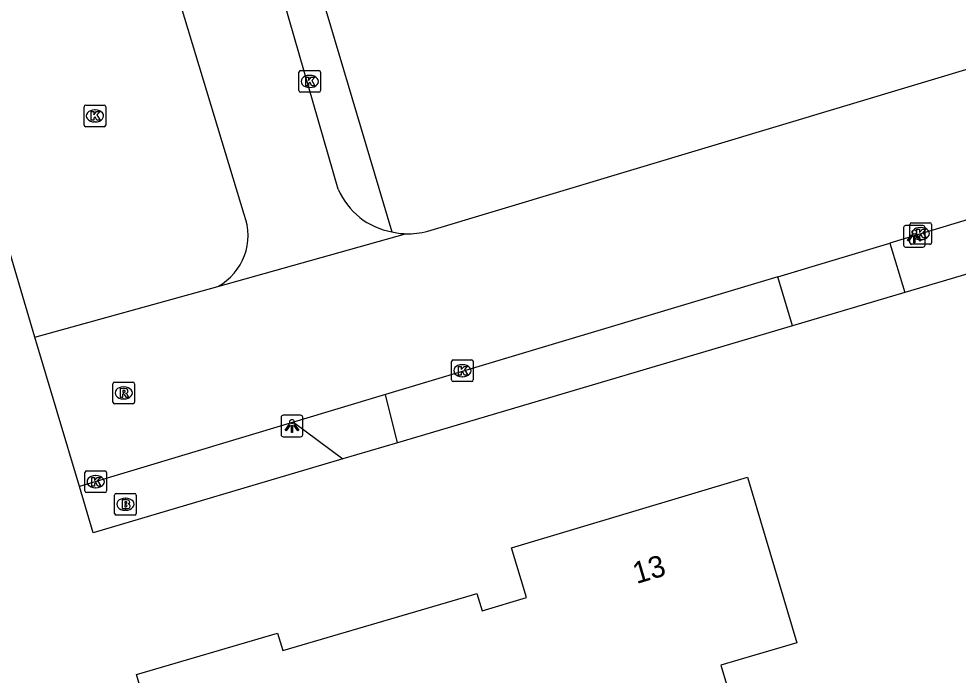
# Model space of a CAD drawing. Extents: x 162417 to 163721, y 384268 to 385416.
# Drawn here: x 163147.13 to 163190.63, y 385083.29 to 385113.7 of the extents above; entities that cross this region are included whole.
import ezdxf

# ---------------------------------------------------------------- set-up
doc = ezdxf.new("R2010")
doc.units = 0
for name, color, linetype in [('IMGEO_Brandkraan', 7, 'Continuous'), ('IMGEO_Groenvoorziening', 7, 'Continuous'), ('IMGEO_Kolk', 7, 'Continuous'), ('IMGEO_Lichtpunt', 7, 'Continuous'), ('IMGEO_Pand', 7, 'Continuous'), ('IMGEO_Pand_nummerreeks', 7, 'Continuous'), ('IMGEO_Parkeervlak_open', 7, 'Continuous'), ('IMGEO_Rijbaan_lokaal_gesloten', 7, 'Continuous'), ('IMGEO_Rioolput', 7, 'Continuous'), ('IMGEO_Voetpad_open', 7, 'Continuous')]:
    doc.layers.add(name, color=color, linetype=linetype)

msp = doc.modelspace()

# ---------------------------------------------------------------- linework, layer by layer
at = {"layer": 'IMGEO_Brandkraan'}
for p, q in [((163151.642, 385091.713), (163152.494, 385091.713)), ((163151.567, 385090.787), (163151.567, 385091.639)), ((163152.055, 385091.493), (163152.08, 385091.493)), ((163152.568, 385091.639), (163152.568, 385090.787)), ((163152.078, 385090.933), (163152.053, 385090.933)), ((163152.494, 385090.713), (163151.642, 385090.713))]:
    msp.add_line(p, q, dxfattribs=at)
for points in [[(163151.642, 385091.713), (163152.494, 385091.713)], [(163151.567, 385090.787), (163151.567, 385091.639)], [(163151.915, 385091.413), (163151.915, 385091.013), (163152.128, 385091.013)], [(163152.146, 385091.413), (163151.915, 385091.413)], [(163152.094, 385091.332), (163152.04, 385091.332), (163152.04, 385091.256)], [(163152.04, 385091.256), (163152.093, 385091.256)], [(163152.568, 385091.639), (163152.568, 385090.787)], [(163152.102, 385091.18), (163152.04, 385091.18), (163152.04, 385091.099)], [(163152.04, 385091.099), (163152.102, 385091.099)], [(163152.494, 385090.713), (163151.642, 385090.713)]]:
    msp.add_lwpolyline(points, dxfattribs=at)
for centre, radius, start, end in [((163151.644, 385091.637), 0.0765, 91.552, 178.448), ((163151.644, 385091.637), 0.0765, 91.552, 178.448), ((163152.492, 385091.637), 0.0765, 1.552, 88.448), ((163152.492, 385091.637), 0.0765, 1.552, 88.448), ((163152.095, 385091.294), 0.0379, 267.8285, 90.9355), ((163152.15, 385091.268), 0.145, 59.4692, 91.5367), ((163152.175, 385091.315), 0.0922, 285.5137, 58.1501), ((163152.103, 385091.139), 0.0404, 269.8759, 90.5077), ((163152.134, 385091.264), 0.251, 268.6676, 293.5347), ((163152.18, 385091.123), 0.105, 301.3115, 78.989), ((163151.644, 385090.789), 0.0765, 181.552, 268.448), ((163151.644, 385090.789), 0.0765, 181.552, 268.448), ((163152.492, 385090.789), 0.0765, 271.552, 358.448), ((163152.492, 385090.789), 0.0765, 271.552, 358.448)]:
    msp.add_arc(centre, radius, start, end, dxfattribs=at)
for centre, major_axis, ratio, start_param, end_param in [((163152.054, 385091.213), (-0.387, 0.002), 0.722429, 4.712389, 7.853982), ((163152.079, 385091.213), (-0.39, 0.002), 0.717154, 1.570796, 4.712389)]:
    msp.add_ellipse(centre, major_axis=major_axis, ratio=ratio, start_param=start_param, end_param=end_param, dxfattribs=at)
at = {"layer": 'IMGEO_Groenvoorziening'}
for points in [[(163159.712, 385119.619), (163164.406, 385103.831)], [(163196.923, 385103.613), (163194.213, 385102.811), (163188.152, 385101.016)], [(163182.959, 385099.479), (163164.667, 385094.062)], [(163162.132, 385093.311), (163150.576, 385089.889), (163149.939, 385092.03)]]:
    msp.add_lwpolyline(points, dxfattribs=at)
at = {"layer": 'IMGEO_Kolk'}
for p, q in [((163160.174, 385111.302), (163161.026, 385111.302)), ((163160.099, 385110.376), (163160.099, 385111.228)), ((163160.587, 385111.082), (163160.612, 385111.082)), ((163161.1, 385111.228), (163161.1, 385110.376)), ((163160.61, 385110.522), (163160.585, 385110.522)), ((163161.026, 385110.302), (163160.174, 385110.302)), ((163150.154, 385108.777), (163150.154, 385109.629)), ((163150.229, 385109.703), (163151.081, 385109.703)), ((163151.155, 385109.629), (163151.155, 385108.777)), ((163150.642, 385109.483), (163150.667, 385109.483)), ((163151.081, 385108.703), (163150.229, 385108.703)), ((163150.665, 385108.923), (163150.64, 385108.923)), ((163188.394, 385103.329), (163188.394, 385104.181)), ((163188.469, 385104.255), (163189.321, 385104.255)), ((163188.882, 385104.035), (163188.907, 385104.035)), ((163189.395, 385104.181), (163189.395, 385103.329)), ((163188.905, 385103.475), (163188.88, 385103.475)), ((163189.321, 385103.255), (163188.469, 385103.255)), ((163167.171, 385096.974), (163167.171, 385097.826)), ((163167.246, 385097.9), (163168.098, 385097.9)), ((163168.172, 385097.826), (163168.172, 385096.974)), ((163167.659, 385097.68), (163167.684, 385097.68)), ((163168.098, 385096.9), (163167.246, 385096.9)), ((163167.682, 385097.12), (163167.657, 385097.12)), ((163150.188, 385091.832), (163150.188, 385092.684)), ((163150.263, 385092.758), (163151.115, 385092.758)), ((163150.676, 385092.538), (163150.701, 385092.538)), ((163151.189, 385092.684), (163151.189, 385091.832)), ((163151.115, 385091.758), (163150.263, 385091.758)), ((163150.699, 385091.978), (163150.674, 385091.978))]:
    msp.add_line(p, q, dxfattribs=at)
for points in [[(163160.174, 385111.302), (163161.026, 385111.302)], [(163160.099, 385110.376), (163160.099, 385111.228)], [(163160.42, 385111.002), (163160.543, 385111.002), (163160.543, 385110.851), (163160.673, 385111.002), (163160.837, 385111.002), (163160.691, 385110.851), (163160.844, 385110.602), (163160.692, 385110.602), (163160.607, 385110.766), (163160.543, 385110.699), (163160.543, 385110.602), (163160.42, 385110.602), (163160.42, 385111.002)], [(163161.1, 385111.228), (163161.1, 385110.376)], [(163161.026, 385110.302), (163160.174, 385110.302)], [(163150.154, 385108.777), (163150.154, 385109.629)], [(163150.229, 385109.703), (163151.081, 385109.703)], [(163151.155, 385109.629), (163151.155, 385108.777)], [(163150.475, 385109.403), (163150.598, 385109.403), (163150.598, 385109.252), (163150.728, 385109.403), (163150.892, 385109.403), (163150.746, 385109.252), (163150.899, 385109.003), (163150.747, 385109.003), (163150.662, 385109.167), (163150.598, 385109.1), (163150.598, 385109.003), (163150.475, 385109.003), (163150.475, 385109.403)], [(163151.081, 385108.703), (163150.229, 385108.703)], [(163188.394, 385103.329), (163188.394, 385104.181)], [(163188.469, 385104.255), (163189.321, 385104.255)], [(163188.715, 385103.955), (163188.838, 385103.955), (163188.838, 385103.804), (163188.968, 385103.955), (163189.132, 385103.955), (163188.986, 385103.804), (163189.139, 385103.555), (163188.987, 385103.555), (163188.902, 385103.719), (163188.838, 385103.652), (163188.838, 385103.555), (163188.715, 385103.555), (163188.715, 385103.955)], [(163189.395, 385104.181), (163189.395, 385103.329)], [(163189.321, 385103.255), (163188.469, 385103.255)], [(163167.171, 385096.974), (163167.171, 385097.826)], [(163167.246, 385097.9), (163168.098, 385097.9)], [(163168.172, 385097.826), (163168.172, 385096.974)], [(163167.492, 385097.6), (163167.615, 385097.6), (163167.615, 385097.449), (163167.745, 385097.6), (163167.909, 385097.6), (163167.763, 385097.449), (163167.916, 385097.2), (163167.764, 385097.2), (163167.679, 385097.364), (163167.615, 385097.297), (163167.615, 385097.2), (163167.492, 385097.2), (163167.492, 385097.6)], [(163168.098, 385096.9), (163167.246, 385096.9)], [(163150.188, 385091.832), (163150.188, 385092.684)], [(163150.263, 385092.758), (163151.115, 385092.758)], [(163151.189, 385092.684), (163151.189, 385091.832)], [(163150.509, 385092.458), (163150.632, 385092.458), (163150.632, 385092.307), (163150.762, 385092.458), (163150.926, 385092.458), (163150.78, 385092.307), (163150.933, 385092.058), (163150.781, 385092.058), (163150.696, 385092.222), (163150.632, 385092.155), (163150.632, 385092.058), (163150.509, 385092.058), (163150.509, 385092.458)], [(163151.115, 385091.758), (163150.263, 385091.758)]]:
    msp.add_lwpolyline(points, dxfattribs=at)
for centre, start, end in [((163160.176, 385111.226), 91.552, 178.448), ((163160.176, 385111.226), 91.552, 178.448), ((163161.024, 385111.226), 1.552, 88.448), ((163161.024, 385111.226), 1.552, 88.448), ((163160.176, 385110.378), 181.552, 268.448), ((163160.176, 385110.378), 181.552, 268.448), ((163161.024, 385110.378), 271.552, 358.448), ((163161.024, 385110.378), 271.552, 358.448), ((163150.231, 385109.627), 91.552, 178.448), ((163150.231, 385109.627), 91.552, 178.448), ((163151.079, 385109.627), 1.552, 88.448), ((163151.079, 385109.627), 1.552, 88.448), ((163150.231, 385108.779), 181.552, 268.448), ((163150.231, 385108.779), 181.552, 268.448), ((163151.079, 385108.779), 271.552, 358.448), ((163151.079, 385108.779), 271.552, 358.448), ((163188.471, 385104.179), 91.552, 178.448), ((163188.471, 385104.179), 91.552, 178.448), ((163189.319, 385104.179), 1.552, 88.448), ((163189.319, 385104.179), 1.552, 88.448), ((163188.471, 385103.331), 181.552, 268.448), ((163188.471, 385103.331), 181.552, 268.448), ((163189.319, 385103.331), 271.552, 358.448), ((163189.319, 385103.331), 271.552, 358.448), ((163167.248, 385097.824), 91.552, 178.448), ((163167.248, 385097.824), 91.552, 178.448), ((163168.096, 385097.824), 1.552, 88.448), ((163168.096, 385097.824), 1.552, 88.448), ((163167.248, 385096.976), 181.552, 268.448), ((163167.248, 385096.976), 181.552, 268.448), ((163168.096, 385096.976), 271.552, 358.448), ((163168.096, 385096.976), 271.552, 358.448), ((163150.265, 385092.682), 91.552, 178.448), ((163150.265, 385092.682), 91.552, 178.448), ((163151.113, 385092.682), 1.552, 88.448), ((163151.113, 385092.682), 1.552, 88.448), ((163150.265, 385091.834), 181.552, 268.448), ((163150.265, 385091.834), 181.552, 268.448), ((163151.113, 385091.834), 271.552, 358.448), ((163151.113, 385091.834), 271.552, 358.448)]:
    msp.add_arc(centre, 0.0765, start, end, dxfattribs=at)
for centre, major_axis, ratio, start_param, end_param in [((163160.586, 385110.802), (-0.387, 0.002), 0.722429, 4.712389, 7.853982), ((163160.611, 385110.802), (-0.39, 0.002), 0.717154, 1.570796, 4.712389), ((163150.641, 385109.203), (-0.387, 0.002), 0.722429, 4.712389, 7.853982), ((163150.666, 385109.203), (-0.39, 0.002), 0.717154, 1.570796, 4.712389), ((163188.881, 385103.755), (-0.387, 0.002), 0.722429, 4.712389, 7.853982), ((163188.906, 385103.755), (-0.39, 0.002), 0.717154, 1.570796, 4.712389), ((163167.658, 385097.4), (-0.387, 0.002), 0.722429, 4.712389, 7.853982), ((163167.683, 385097.4), (-0.39, 0.002), 0.717154, 1.570796, 4.712389), ((163150.675, 385092.258), (-0.387, 0.002), 0.722429, 4.712389, 7.853982), ((163150.7, 385092.258), (-0.39, 0.002), 0.717154, 1.570796, 4.712389)]:
    msp.add_ellipse(centre, major_axis=major_axis, ratio=ratio, start_param=start_param, end_param=end_param, dxfattribs=at)
at = {"layer": 'IMGEO_Lichtpunt'}
for p, q in [((163188.096, 385104.027), (163188.096, 385103.22)), ((163188.096, 385104.027), (163188.096, 385103.22)), ((163188.998, 385104.122), (163188.19, 385104.122)), ((163188.998, 385104.122), (163188.19, 385104.122)), ((163189.092, 385103.22), (163189.092, 385104.027)), ((163189.092, 385103.22), (163189.092, 385104.027)), ((163188.19, 385103.126), (163188.998, 385103.126)), ((163188.19, 385103.126), (163188.998, 385103.126)), ((163159.278, 385095.243), (163159.278, 385094.436)), ((163159.278, 385095.243), (163159.278, 385094.436)), ((163160.18, 385095.338), (163159.372, 385095.338)), ((163160.18, 385095.338), (163159.372, 385095.338)), ((163160.274, 385094.436), (163160.274, 385095.243)), ((163160.274, 385094.436), (163160.274, 385095.243)), ((163159.372, 385094.342), (163160.18, 385094.342)), ((163159.372, 385094.342), (163160.18, 385094.342))]:
    msp.add_line(p, q, dxfattribs=at)
for points in [[(163188.47, 385103.691), (163188.509, 385103.663), (163188.321, 385103.401), (163188.283, 385103.428), (163188.47, 385103.691)], [(163188.572, 385103.643), (163188.619, 385103.643), (163188.619, 385103.321), (163188.572, 385103.321), (163188.572, 385103.643)], [(163188.682, 385103.663), (163188.72, 385103.69), (163188.907, 385103.428), (163188.868, 385103.4), (163188.682, 385103.663)], [(163159.652, 385094.907), (163159.691, 385094.879), (163159.503, 385094.617), (163159.465, 385094.644), (163159.652, 385094.907)], [(163159.754, 385094.859), (163159.801, 385094.859), (163159.801, 385094.537), (163159.754, 385094.537), (163159.754, 385094.859)], [(163159.864, 385094.879), (163159.902, 385094.906), (163160.089, 385094.644), (163160.05, 385094.616), (163159.864, 385094.879)]]:
    msp.add_lwpolyline(points, dxfattribs=at)
for centre in [(163188.595, 385103.825), (163159.777, 385095.041)]:
    msp.add_circle(centre, 0.0994, dxfattribs=at)
for centre, start, end in [((163188.19, 385104.027), 90, 180), ((163188.19, 385104.027), 90, 180), ((163188.998, 385104.027), 0, 90), ((163188.998, 385104.027), 0, 90), ((163188.19, 385103.22), 180, 270), ((163188.19, 385103.22), 180, 270), ((163188.998, 385103.22), 270, 0), ((163188.998, 385103.22), 270, 360), ((163159.372, 385095.243), 90, 180), ((163159.372, 385095.243), 90, 180), ((163160.18, 385095.243), 0, 90), ((163160.18, 385095.243), 0, 90), ((163159.372, 385094.436), 180, 270), ((163159.372, 385094.436), 180, 270), ((163160.18, 385094.436), 270, 0), ((163160.18, 385094.436), 270, 360)]:
    msp.add_arc(centre, 0.0946, start, end, dxfattribs=at)
at = {"layer": 'IMGEO_Pand'}
for points in [[(163156.31, 385070.625), (163152.582, 385083.323), (163159.115, 385085.241), (163159.36, 385084.431), (163168.092, 385087.005), (163168.34, 385087.078), (163168.584, 385086.271), (163170.631, 385086.89), (163169.936, 385089.198), (163180.876, 385092.471)], [(163180.876, 385092.471), (163183.16, 385084.799), (163179.644, 385083.752), (163181.304, 385078.176)]]:
    msp.add_lwpolyline(points, dxfattribs=at)
at = {"layer": 'IMGEO_Parkeervlak_open'}
msp.add_lwpolyline([(163147.876, 385098.953), (163145.757, 385106.075)], dxfattribs=at)
at = {"layer": 'IMGEO_Rijbaan_lokaal_gesloten'}
for points in [[(163157.566, 385104.63), (163148.465, 385134.746)], [(163166.066, 385103.869), (163265.986, 385133.92)], [(163161.924, 385105.803), (163158.075, 385119.146)], [(163196.22, 385105.951), (163193.536, 385105.144), (163187.46, 385103.316)], [(163156.341, 385101.298), (163165.035, 385103.746)], [(163182.274, 385101.756), (163187.46, 385103.316)], [(163182.274, 385101.756), (163164.109, 385096.292)], [(163147.876, 385098.953), (163156.341, 385101.298)], [(163149.939, 385092.03), (163147.876, 385098.953)], [(163164.109, 385096.292), (163159.847, 385095.01)], [(163159.847, 385095.01), (163149.939, 385092.03)]]:
    msp.add_lwpolyline(points, dxfattribs=at)
for centre, radius, start, end in [((163164.993, 385107.118), 3.339, 203.1941, 259.8702), ((163155.041, 385103.667), 2.703, 298.7602, 20.8682), ((163165.169, 385107.008), 3.265, 267.654, 285.9527), ((163165.149, 385106.96), 3.216, 256.6414, 267.9665)]:
    msp.add_arc(centre, radius, start, end, dxfattribs=at)
at = {"layer": 'IMGEO_Rioolput'}
for p, q in [((163151.489, 385095.944), (163151.489, 385096.796)), ((163151.564, 385096.87), (163152.416, 385096.87)), ((163151.977, 385096.65), (163152.002, 385096.65)), ((163152.49, 385096.796), (163152.49, 385095.944)), ((163152, 385096.09), (163151.975, 385096.09)), ((163152.416, 385095.87), (163151.564, 385095.87))]:
    msp.add_line(p, q, dxfattribs=at)
for points in [[(163151.489, 385095.944), (163151.489, 385096.796)], [(163151.564, 385096.87), (163152.416, 385096.87)], [(163152.078, 385096.568), (163151.826, 385096.57), (163151.826, 385096.17)], [(163152.004, 385096.489), (163151.95, 385096.489), (163151.95, 385096.408)], [(163152.49, 385096.796), (163152.49, 385095.944)], [(163151.826, 385096.17), (163151.95, 385096.17), (163151.95, 385096.332), (163151.961, 385096.332)], [(163151.95, 385096.408), (163152.002, 385096.408)], [(163152.008, 385096.303), (163152.079, 385096.17), (163152.219, 385096.17), (163152.154, 385096.296)], [(163152.416, 385095.87), (163151.564, 385095.87)]]:
    msp.add_lwpolyline(points, dxfattribs=at)
for centre, radius, start, end in [((163151.566, 385096.794), 0.0765, 91.552, 178.448), ((163151.566, 385096.794), 0.0765, 91.552, 178.448), ((163152.01, 385096.393), 0.0964, 77.0061, 93.1865), ((163152.024, 385096.45), 0.0378, 276.6634, 79.6772), ((163152.077, 385096.458), 0.109, 350.3612, 89.416), ((163152.414, 385096.794), 0.0765, 1.552, 88.448), ((163152.414, 385096.794), 0.0765, 1.552, 88.448), ((163151.96, 385096.279), 0.0533, 26.0293, 88.6989), ((163151.986, 385096.597), 0.19, 274.7715, 282.9687), ((163152.075, 385096.458), 0.112, 277.5842, 350.9817), ((163152.059, 385096.243), 0.108, 29.5134, 73.7905), ((163151.566, 385095.946), 0.0765, 181.552, 268.448), ((163151.566, 385095.946), 0.0765, 181.552, 268.448), ((163152.414, 385095.946), 0.0765, 271.552, 358.448), ((163152.414, 385095.946), 0.0765, 271.552, 358.448)]:
    msp.add_arc(centre, radius, start, end, dxfattribs=at)
for centre, major_axis, ratio, start_param, end_param in [((163151.976, 385096.37), (-0.387, 0.002), 0.722429, 4.712389, 7.853982), ((163152.001, 385096.37), (-0.39, 0.002), 0.717154, 1.570796, 4.712389)]:
    msp.add_ellipse(centre, major_axis=major_axis, ratio=ratio, start_param=start_param, end_param=end_param, dxfattribs=at)
at = {"layer": 'IMGEO_Voetpad_open'}
for points in [[(163187.46, 385103.316), (163188.152, 385101.016)], [(163182.959, 385099.479), (163182.274, 385101.756)], [(163188.152, 385101.016), (163182.959, 385099.479)], [(163164.667, 385094.062), (163164.109, 385096.292)], [(163159.847, 385095.01), (163162.132, 385093.311)], [(163164.667, 385094.062), (163162.132, 385093.311)]]:
    msp.add_lwpolyline(points, dxfattribs=at)

# ---------------------------------------------------------------- texts
at = {"layer": 'IMGEO_Pand_nummerreeks'}
msp.add_text('13', height=1, rotation=16.6043, dxfattribs=at).set_placement((163175.735, 385087.515))

doc.saveas('drawing.dxf')
